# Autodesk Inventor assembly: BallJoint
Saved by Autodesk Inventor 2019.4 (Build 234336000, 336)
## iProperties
Created: 2020-04
Part Number: BallJoint
Document SubType Name: Assembly
Designer: Administrator
Title: BallJoint v14
Author: Administrator
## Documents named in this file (3)
- c:\worker\convert-fusion-r03\tmp\job-1\48\output\files\ccae6ef3-9f0e-42ff-b199-3a2c6474057a\BallJoint v14.iam
- c:\worker\convert-fusion-r03\tmp\job-1\48\output\files\ccae6ef3-9f0e-42ff-b199-3a2c6474057a\Component1_1.ipt
- c:\worker\convert-fusion-r03\tmp\job-1\48\output\files\ccae6ef3-9f0e-42ff-b199-3a2c6474057a\Component2_1.ipt
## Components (2 placed, 2 different names)
1. Component1:1
2. Component2:1
